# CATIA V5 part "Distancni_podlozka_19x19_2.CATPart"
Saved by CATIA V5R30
Part number: Distancni_podlozka_19x19_2
Definition: EH 6281_19x19_1
Nomenclature: EH 6281_19x19_1
Source: Unknown
Description: PART--DESC
Bounding box of the stored display mesh (mm): x 120 to 139, y -27.99 to -9.01, z 20.7 to 39.7
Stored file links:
  E:\Bakalarka\Model\Forma_v7\Distancni_podlozka_19x19_2.CATPart
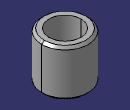
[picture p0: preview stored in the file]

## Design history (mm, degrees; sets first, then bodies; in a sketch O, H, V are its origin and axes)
Body1 "MANIFOLD_SOLID_BREP #3722" (main body)
  Solid1: solid without history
